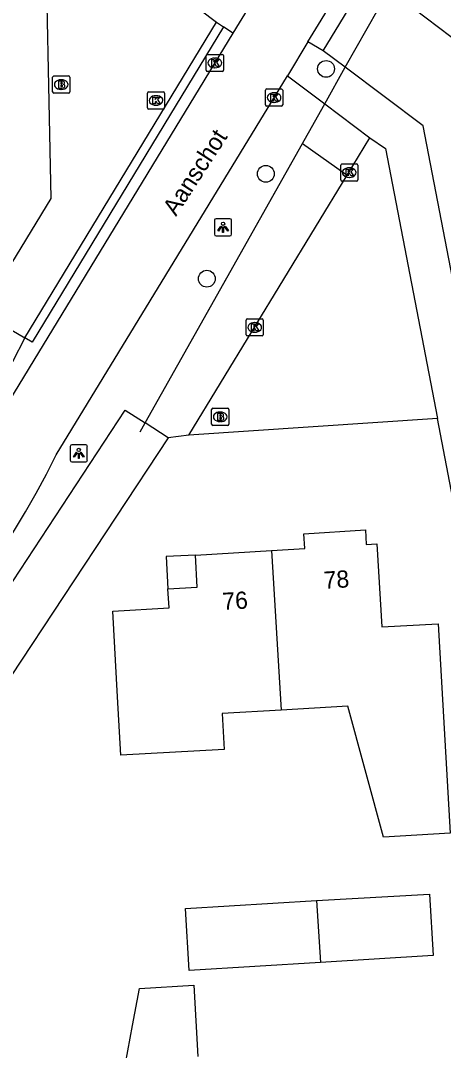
# Model space of a CAD drawing. Extents: x 159628 to 160723, y 388176 to 389416.
# Drawn here: x 160393.4 to 160418, y 388521 to 388580.9 of the extents above; entities that cross this region are included whole.
import ezdxf

# ---------------------------------------------------------------- set-up
doc = ezdxf.new("R2010")
doc.units = 0
for name, color, linetype in [('IMGEO_Berm_groen', 7, 'Continuous'), ('IMGEO_Boom', 7, 'Continuous'), ('IMGEO_Brandkraan', 7, 'Continuous'), ('IMGEO_Duiker', 7, 'Continuous'), ('IMGEO_Fietspad_gesloten', 7, 'Continuous'), ('IMGEO_Groenvoorziening', 7, 'Continuous'), ('IMGEO_Haag', 7, 'Continuous'), ('IMGEO_Kolk', 7, 'Continuous'), ('IMGEO_Lichtpunt', 7, 'Continuous'), ('IMGEO_Openbare_ruimte_label', 7, 'Continuous'), ('IMGEO_Pand', 7, 'Continuous'), ('IMGEO_Pand_nummerreeks', 7, 'Continuous'), ('IMGEO_Pand_overbouw', 7, 'Continuous'), ('IMGEO_Rijbaan_lokaal_open', 7, 'Continuous'), ('IMGEO_Voetpad_open', 7, 'Continuous'), ('IMGEO_Waterloop', 7, 'Continuous')]:
    doc.layers.add(name, color=color, linetype=linetype)

msp = doc.modelspace()

# ---------------------------------------------------------------- linework, layer by layer
at = {"layer": 'IMGEO_Berm_groen'}
for points in [[(160400.605, 388557.491), (160409.76, 388573.745), (160412.374, 388571.905)], [(160393.603, 388562.441), (160392.884, 388561.036)]]:
    msp.add_lwpolyline(points, dxfattribs=at)
at = {"layer": 'IMGEO_Boom'}
for centre in [(160411.138, 388578.087), (160407.635, 388571.983), (160404.196, 388565.881)]:
    msp.add_circle(centre, 0.489, dxfattribs=at)
at = {"layer": 'IMGEO_Brandkraan'}
for p, q in [((160395.223, 388576.751), (160395.223, 388577.603)), ((160395.298, 388577.677), (160396.15, 388577.677)), ((160395.711, 388577.457), (160395.736, 388577.457)), ((160396.224, 388577.603), (160396.224, 388576.751)), ((160395.734, 388576.897), (160395.709, 388576.897)), ((160396.15, 388576.677), (160395.298, 388576.677)), ((160404.479, 388557.418), (160404.479, 388558.27)), ((160404.554, 388558.344), (160405.406, 388558.344)), ((160405.48, 388558.27), (160405.48, 388557.418)), ((160404.99, 388557.564), (160404.965, 388557.564)), ((160404.967, 388558.124), (160404.992, 388558.124)), ((160405.406, 388557.344), (160404.554, 388557.344))]:
    msp.add_line(p, q, dxfattribs=at)
for points in [[(160395.223, 388576.751), (160395.223, 388577.603)], [(160395.298, 388577.677), (160396.15, 388577.677)], [(160395.571, 388577.377), (160395.571, 388576.977), (160395.784, 388576.977)], [(160395.802, 388577.377), (160395.571, 388577.377)], [(160396.224, 388577.603), (160396.224, 388576.751)], [(160395.75, 388577.296), (160395.696, 388577.296), (160395.696, 388577.22)], [(160395.696, 388577.22), (160395.749, 388577.22)], [(160395.758, 388577.144), (160395.696, 388577.144), (160395.696, 388577.063)], [(160395.696, 388577.063), (160395.758, 388577.063)], [(160396.15, 388576.677), (160395.298, 388576.677)], [(160404.479, 388557.418), (160404.479, 388558.27)], [(160404.554, 388558.344), (160405.406, 388558.344)], [(160405.48, 388558.27), (160405.48, 388557.418)], [(160404.827, 388558.044), (160404.827, 388557.644), (160405.04, 388557.644)], [(160405.058, 388558.044), (160404.827, 388558.044)], [(160405.006, 388557.963), (160404.952, 388557.963), (160404.952, 388557.887)], [(160404.952, 388557.887), (160405.005, 388557.887)], [(160405.014, 388557.811), (160404.952, 388557.811), (160404.952, 388557.73)], [(160404.952, 388557.73), (160405.014, 388557.73)], [(160405.406, 388557.344), (160404.554, 388557.344)]]:
    msp.add_lwpolyline(points, dxfattribs=at)
for centre, radius, start, end in [((160395.3, 388577.601), 0.0765, 91.55205, 178.44795), ((160395.3, 388577.601), 0.0765, 91.55205, 178.44795), ((160395.806, 388577.232), 0.145, 59.4692, 91.53667), ((160395.831, 388577.279), 0.0922, 285.51372, 58.15012), ((160396.148, 388577.601), 0.0765, 1.55205, 88.44795), ((160396.148, 388577.601), 0.0765, 1.55205, 88.44795), ((160395.3, 388576.753), 0.0765, 181.55205, 268.44795), ((160395.3, 388576.753), 0.0765, 181.55205, 268.44795), ((160395.751, 388577.258), 0.0379, 267.82845, 90.93552), ((160395.759, 388577.103), 0.0404, 269.87594, 90.50774), ((160395.79, 388577.228), 0.251, 268.66757, 293.53466), ((160395.836, 388577.087), 0.105, 301.31148, 78.98903), ((160396.148, 388576.753), 0.0765, 271.55205, 358.44795), ((160396.148, 388576.753), 0.0765, 271.55205, 358.44795), ((160404.556, 388558.268), 0.0765, 91.55205, 178.44795), ((160404.556, 388558.268), 0.0765, 91.55205, 178.44795), ((160405.404, 388558.268), 0.0765, 1.55205, 88.44795), ((160405.404, 388558.268), 0.0765, 1.55205, 88.44795), ((160405.007, 388557.925), 0.0379, 267.82845, 90.93552), ((160405.015, 388557.77), 0.0404, 269.87594, 90.50774), ((160405.046, 388557.895), 0.251, 268.66757, 293.53466), ((160405.062, 388557.899), 0.145, 59.4692, 91.53667), ((160405.087, 388557.946), 0.0922, 285.51372, 58.15012), ((160405.092, 388557.754), 0.105, 301.31148, 78.98903), ((160404.556, 388557.42), 0.0765, 181.55205, 268.44795), ((160404.556, 388557.42), 0.0765, 181.55205, 268.44795), ((160405.404, 388557.42), 0.0765, 271.55205, 358.44795), ((160405.404, 388557.42), 0.0765, 271.55205, 358.44795)]:
    msp.add_arc(centre, radius, start, end, dxfattribs=at)
for centre, major_axis, ratio, start_param, end_param in [((160395.71, 388577.177), (-0.387, 0.002), 0.722429, 4.712389, 7.853982), ((160395.735, 388577.177), (-0.39, 0.002), 0.717154, 1.570796, 4.712389), ((160404.966, 388557.844), (-0.387, 0.002), 0.722429, 4.712389, 7.853982), ((160404.991, 388557.844), (-0.39, 0.002), 0.717154, 1.570796, 4.712389)]:
    msp.add_ellipse(centre, major_axis=major_axis, ratio=ratio, start_param=start_param, end_param=end_param, dxfattribs=at)
at = {"layer": 'IMGEO_Duiker'}
msp.add_lwpolyline([(160400.316, 388556.978), (160400.605, 388557.491), (160411.06, 388576.054), (160412.259, 388578.184), (160414.806, 388582.706), (160416.017, 388584.856), (160416.544, 388585.792), (160416.623, 388585.932)], dxfattribs=at)
at = {"layer": 'IMGEO_Fietspad_gesloten'}
for points in [[(160406.613, 388581.63), (160405.715, 388580.159)], [(160405.715, 388580.159), (160392.155, 388557.919)], [(160410.081, 388579.662), (160408.889, 388577.691)], [(160395.428, 388555.636), (160408.889, 388577.691)]]:
    msp.add_lwpolyline(points, dxfattribs=at)
msp.add_arc((160346.289, 388579.991), 54.844, 291.95332, 333.63542, dxfattribs=at)
at = {"layer": 'IMGEO_Groenvoorziening'}
msp.add_lwpolyline([(160403.151, 388556.78), (160401.953, 388556.623)], dxfattribs=at)
at = {"layer": 'IMGEO_Haag'}
msp.add_lwpolyline([(160405.169, 388580.532), (160394.03, 388562.182), (160393.603, 388562.441)], dxfattribs=at)
at = {"layer": 'IMGEO_Kolk'}
for p, q in [((160404.163, 388578.009), (160404.163, 388578.861)), ((160404.238, 388578.935), (160405.09, 388578.935)), ((160404.651, 388578.715), (160404.676, 388578.715)), ((160405.164, 388578.861), (160405.164, 388578.009)), ((160405.09, 388577.935), (160404.238, 388577.935)), ((160404.674, 388578.155), (160404.649, 388578.155)), ((160400.814, 388576.751), (160401.666, 388576.751)), ((160407.612, 388575.994), (160407.612, 388576.846)), ((160407.687, 388576.92), (160408.539, 388576.92)), ((160408.613, 388576.846), (160408.613, 388575.994)), ((160400.739, 388575.825), (160400.739, 388576.677)), ((160401.227, 388576.531), (160401.252, 388576.531)), ((160401.74, 388576.677), (160401.74, 388575.825)), ((160408.123, 388576.14), (160408.098, 388576.14)), ((160408.1, 388576.7), (160408.125, 388576.7)), ((160401.666, 388575.751), (160400.814, 388575.751)), ((160401.25, 388575.971), (160401.225, 388575.971)), ((160408.539, 388575.92), (160407.687, 388575.92)), ((160412.066, 388572.557), (160412.918, 388572.557)), ((160411.991, 388571.631), (160411.991, 388572.483)), ((160412.479, 388572.337), (160412.504, 388572.337)), ((160412.992, 388572.483), (160412.992, 388571.631)), ((160412.918, 388571.557), (160412.066, 388571.557)), ((160412.502, 388571.777), (160412.477, 388571.777)), ((160406.559, 388563.548), (160407.411, 388563.548)), ((160406.484, 388562.622), (160406.484, 388563.474)), ((160406.972, 388563.328), (160406.997, 388563.328)), ((160407.485, 388563.474), (160407.485, 388562.622)), ((160407.411, 388562.548), (160406.559, 388562.548)), ((160406.995, 388562.768), (160406.97, 388562.768))]:
    msp.add_line(p, q, dxfattribs=at)
for points in [[(160404.163, 388578.009), (160404.163, 388578.861)], [(160404.238, 388578.935), (160405.09, 388578.935)], [(160404.484, 388578.635), (160404.607, 388578.635), (160404.607, 388578.484), (160404.737, 388578.635), (160404.901, 388578.635), (160404.755, 388578.484), (160404.908, 388578.235), (160404.756, 388578.235), (160404.671, 388578.399), (160404.607, 388578.332), (160404.607, 388578.235), (160404.484, 388578.235), (160404.484, 388578.635)], [(160405.164, 388578.861), (160405.164, 388578.009)], [(160405.09, 388577.935), (160404.238, 388577.935)], [(160400.814, 388576.751), (160401.666, 388576.751)], [(160407.612, 388575.994), (160407.612, 388576.846)], [(160407.687, 388576.92), (160408.539, 388576.92)], [(160408.613, 388576.846), (160408.613, 388575.994)], [(160400.739, 388575.825), (160400.739, 388576.677)], [(160401.06, 388576.451), (160401.183, 388576.451), (160401.183, 388576.3), (160401.313, 388576.451), (160401.477, 388576.451), (160401.331, 388576.3), (160401.484, 388576.051), (160401.332, 388576.051), (160401.247, 388576.215), (160401.183, 388576.148), (160401.183, 388576.051), (160401.06, 388576.051), (160401.06, 388576.451)], [(160401.74, 388576.677), (160401.74, 388575.825)], [(160407.933, 388576.62), (160408.056, 388576.62), (160408.056, 388576.469), (160408.186, 388576.62), (160408.35, 388576.62), (160408.204, 388576.469), (160408.357, 388576.22), (160408.205, 388576.22), (160408.12, 388576.384), (160408.056, 388576.317), (160408.056, 388576.22), (160407.933, 388576.22), (160407.933, 388576.62)], [(160401.666, 388575.751), (160400.814, 388575.751)], [(160408.539, 388575.92), (160407.687, 388575.92)], [(160412.066, 388572.557), (160412.918, 388572.557)], [(160411.991, 388571.631), (160411.991, 388572.483)], [(160412.312, 388572.257), (160412.435, 388572.257), (160412.435, 388572.106), (160412.565, 388572.257), (160412.729, 388572.257), (160412.583, 388572.106), (160412.736, 388571.857), (160412.584, 388571.857), (160412.499, 388572.021), (160412.435, 388571.954), (160412.435, 388571.857), (160412.312, 388571.857), (160412.312, 388572.257)], [(160412.992, 388572.483), (160412.992, 388571.631)], [(160412.918, 388571.557), (160412.066, 388571.557)], [(160406.559, 388563.548), (160407.411, 388563.548)], [(160406.484, 388562.622), (160406.484, 388563.474)], [(160406.805, 388563.248), (160406.928, 388563.248), (160406.928, 388563.097), (160407.058, 388563.248), (160407.222, 388563.248), (160407.076, 388563.097), (160407.229, 388562.848), (160407.077, 388562.848), (160406.992, 388563.012), (160406.928, 388562.945), (160406.928, 388562.848), (160406.805, 388562.848), (160406.805, 388563.248)], [(160407.485, 388563.474), (160407.485, 388562.622)], [(160407.411, 388562.548), (160406.559, 388562.548)]]:
    msp.add_lwpolyline(points, dxfattribs=at)
for centre, start, end in [((160404.24, 388578.859), 91.55205, 178.44795), ((160404.24, 388578.859), 91.55205, 178.44795), ((160405.088, 388578.859), 1.55205, 88.44795), ((160405.088, 388578.859), 1.55205, 88.44795), ((160404.24, 388578.011), 181.55205, 268.44795), ((160404.24, 388578.011), 181.55205, 268.44795), ((160405.088, 388578.011), 271.55205, 358.44795), ((160405.088, 388578.011), 271.55205, 358.44795), ((160400.816, 388576.675), 91.55205, 178.44795), ((160400.816, 388576.675), 91.55205, 178.44795), ((160401.664, 388576.675), 1.55205, 88.44795), ((160401.664, 388576.675), 1.55205, 88.44795), ((160407.689, 388576.844), 91.55205, 178.44795), ((160407.689, 388576.844), 91.55205, 178.44795), ((160408.537, 388576.844), 1.55205, 88.44795), ((160408.537, 388576.844), 1.55205, 88.44795), ((160400.816, 388575.827), 181.55205, 268.44795), ((160400.816, 388575.827), 181.55205, 268.44795), ((160401.664, 388575.827), 271.55205, 358.44795), ((160401.664, 388575.827), 271.55205, 358.44795), ((160407.689, 388575.996), 181.55205, 268.44795), ((160407.689, 388575.996), 181.55205, 268.44795), ((160408.537, 388575.996), 271.55205, 358.44795), ((160408.537, 388575.996), 271.55205, 358.44795), ((160412.068, 388572.481), 91.55205, 178.44795), ((160412.068, 388572.481), 91.55205, 178.44795), ((160412.916, 388572.481), 1.55205, 88.44795), ((160412.916, 388572.481), 1.55205, 88.44795), ((160412.068, 388571.633), 181.55205, 268.44795), ((160412.068, 388571.633), 181.55205, 268.44795), ((160412.916, 388571.633), 271.55205, 358.44795), ((160412.916, 388571.633), 271.55205, 358.44795), ((160406.561, 388563.472), 91.55205, 178.44795), ((160406.561, 388563.472), 91.55205, 178.44795), ((160407.409, 388563.472), 1.55205, 88.44795), ((160407.409, 388563.472), 1.55205, 88.44795), ((160406.561, 388562.624), 181.55205, 268.44795), ((160406.561, 388562.624), 181.55205, 268.44795), ((160407.409, 388562.624), 271.55205, 358.44795), ((160407.409, 388562.624), 271.55205, 358.44795)]:
    msp.add_arc(centre, 0.0765, start, end, dxfattribs=at)
for centre, major_axis, ratio, start_param, end_param in [((160404.65, 388578.435), (-0.387, 0.002), 0.722429, 4.712389, 7.853982), ((160404.675, 388578.435), (-0.39, 0.002), 0.717154, 1.570796, 4.712389), ((160401.226, 388576.251), (-0.387, 0.002), 0.722429, 4.712389, 7.853982), ((160401.251, 388576.251), (-0.39, 0.002), 0.717154, 1.570796, 4.712389), ((160408.099, 388576.42), (-0.387, 0.002), 0.722429, 4.712389, 7.853982), ((160408.124, 388576.42), (-0.39, 0.002), 0.717154, 1.570796, 4.712389), ((160412.478, 388572.057), (-0.387, 0.002), 0.722429, 4.712389, 7.853982), ((160412.503, 388572.057), (-0.39, 0.002), 0.717154, 1.570796, 4.712389), ((160406.971, 388563.048), (-0.387, 0.002), 0.722429, 4.712389, 7.853982), ((160406.996, 388563.048), (-0.39, 0.002), 0.717154, 1.570796, 4.712389)]:
    msp.add_ellipse(centre, major_axis=major_axis, ratio=ratio, start_param=start_param, end_param=end_param, dxfattribs=at)
at = {"layer": 'IMGEO_Lichtpunt'}
for p, q in [((160404.644, 388569.278), (160404.644, 388568.471)), ((160404.644, 388569.278), (160404.644, 388568.471)), ((160405.546, 388569.373), (160404.738, 388569.373)), ((160405.546, 388569.373), (160404.738, 388569.373)), ((160405.64, 388568.471), (160405.64, 388569.278)), ((160405.64, 388568.471), (160405.64, 388569.278)), ((160404.738, 388568.377), (160405.546, 388568.377)), ((160404.738, 388568.377), (160405.546, 388568.377)), ((160396.246, 388556.121), (160396.246, 388555.314)), ((160396.246, 388556.121), (160396.246, 388555.314)), ((160397.148, 388556.216), (160396.34, 388556.216)), ((160397.148, 388556.216), (160396.34, 388556.216)), ((160397.242, 388555.314), (160397.242, 388556.121)), ((160397.242, 388555.314), (160397.242, 388556.121)), ((160396.34, 388555.22), (160397.148, 388555.22)), ((160396.34, 388555.22), (160397.148, 388555.22))]:
    msp.add_line(p, q, dxfattribs=at)
for points in [[(160405.018, 388568.942), (160405.057, 388568.914), (160404.869, 388568.652), (160404.831, 388568.679), (160405.018, 388568.942)], [(160405.23, 388568.914), (160405.268, 388568.941), (160405.455, 388568.679), (160405.416, 388568.651), (160405.23, 388568.914)], [(160405.12, 388568.894), (160405.167, 388568.894), (160405.167, 388568.572), (160405.12, 388568.572), (160405.12, 388568.894)], [(160396.62, 388555.785), (160396.659, 388555.757), (160396.471, 388555.495), (160396.433, 388555.522), (160396.62, 388555.785)], [(160396.832, 388555.757), (160396.87, 388555.784), (160397.057, 388555.522), (160397.018, 388555.494), (160396.832, 388555.757)], [(160396.722, 388555.737), (160396.769, 388555.737), (160396.769, 388555.415), (160396.722, 388555.415), (160396.722, 388555.737)]]:
    msp.add_lwpolyline(points, dxfattribs=at)
for centre in [(160405.143, 388569.076), (160396.745, 388555.919)]:
    msp.add_circle(centre, 0.0994, dxfattribs=at)
for centre, start, end in [((160404.738, 388569.278), 90, 180), ((160404.738, 388569.278), 90, 180), ((160405.546, 388569.278), 0, 90), ((160405.546, 388569.278), 0, 90), ((160404.738, 388568.471), 180, 270), ((160404.738, 388568.471), 180, 270), ((160405.546, 388568.471), 270, 0), ((160405.546, 388568.471), 270, 360), ((160396.34, 388556.121), 90, 180), ((160396.34, 388556.121), 90, 180), ((160397.148, 388556.121), 0, 90), ((160397.148, 388556.121), 0, 90), ((160396.34, 388555.314), 180, 270), ((160396.34, 388555.314), 180, 270), ((160397.148, 388555.314), 270, 0), ((160397.148, 388555.314), 270, 360)]:
    msp.add_arc(centre, 0.0946, start, end, dxfattribs=at)
at = {"layer": 'IMGEO_Pand'}
for points in [[(160407.967, 388550.067), (160409.903, 388550.188), (160409.849, 388551.044), (160413.432, 388551.275), (160413.481, 388550.416), (160414.101, 388550.451), (160414.377, 388545.617), (160417.674, 388545.804), (160418.366, 388533.614), (160414.483, 388533.394), (160412.414, 388541.006), (160408.516, 388540.785)], [(160408.516, 388540.785), (160405.082, 388540.59), (160405.201, 388538.492), (160399.197, 388538.152), (160399.004, 388541.554), (160398.721, 388546.545), (160401.999, 388546.733), (160401.937, 388547.831), (160403.637, 388547.929), (160403.533, 388549.79), (160407.967, 388550.067)], [(160407.967, 388550.067), (160408.516, 388540.785)], [(160410.588, 388529.703), (160417.16, 388530.067), (160417.379, 388526.493), (160410.811, 388526.089)], [(160410.811, 388526.089), (160403.178, 388525.62), (160402.957, 388529.235), (160410.588, 388529.703)], [(160410.588, 388529.703), (160410.811, 388526.089)], [(160404.559, 388505.251), (160401.403, 388505.039), (160401.478, 388503.932), (160399.726, 388503.815), (160399.851, 388501.965), (160395.266, 388501.702), (160394.889, 388507.998), (160394.62, 388507.983), (160394.482, 388510.278), (160394.752, 388510.295), (160394.711, 388510.994), (160398.304, 388511.209), (160398.178, 388513.305), (160398.368, 388514.324), (160399.879, 388522.423), (160400.282, 388524.588), (160403.45, 388524.773), (160403.682, 388520.619)]]:
    msp.add_lwpolyline(points, dxfattribs=at)
at = {"layer": 'IMGEO_Pand_overbouw'}
msp.add_lwpolyline([(160401.937, 388547.831), (160403.637, 388547.929), (160403.533, 388549.79), (160401.833, 388549.712)], close=True, dxfattribs=at)
at = {"layer": 'IMGEO_Rijbaan_lokaal_open'}
for points in [[(160410.081, 388579.662), (160413.303, 388584.911)], [(160410.98, 388579.143), (160413.658, 388583.58)], [(160413.658, 388583.58), (160414.806, 388582.706), (160419.837, 388578.879), (160420.072, 388578.69)], [(160410.98, 388579.143), (160410.081, 388579.662)], [(160421.804, 388548.844), (160416.794, 388574.782), (160412.259, 388578.184), (160410.98, 388579.143)]]:
    msp.add_lwpolyline(points, dxfattribs=at)
at = {"layer": 'IMGEO_Voetpad_open'}
for points in [[(160391.082, 388563.91), (160395.137, 388570.551), (160394.778, 388588.369)], [(160394.778, 388588.369), (160404.756, 388580.814)], [(160393.603, 388562.441), (160404.756, 388580.814)], [(160404.756, 388580.814), (160405.169, 388580.532)], [(160405.715, 388580.159), (160405.169, 388580.532)], [(160408.889, 388577.691), (160411.06, 388576.054), (160413.693, 388574.069)], [(160412.374, 388571.905), (160413.693, 388574.069)], [(160413.693, 388574.069), (160414.591, 388573.459), (160417.623, 388557.739)], [(160403.151, 388556.78), (160412.374, 388571.905)], [(160391.082, 388563.91), (160393.603, 388562.441)], [(160417.623, 388557.739), (160403.151, 388556.78)], [(160428.536, 388500), (160428.603, 388500.275), (160428.603, 388500.573), (160427.081, 388508.495), (160423.552, 388526.872), (160417.623, 388557.739)]]:
    msp.add_lwpolyline(points, dxfattribs=at)
at = {"layer": 'IMGEO_Waterloop'}
for points in [[(160390.866, 388545.19), (160399.448, 388558.235), (160400.605, 388557.491)], [(160401.953, 388556.623), (160400.605, 388557.491)], [(160401.953, 388556.623), (160392.807, 388542.778)]]:
    msp.add_lwpolyline(points, dxfattribs=at)

# ---------------------------------------------------------------- texts
at = {"layer": 'IMGEO_Openbare_ruimte_label'}
msp.add_text('Aanschot', height=1, rotation=57.04099, dxfattribs=at).set_placement((160402.404, 388569.47))
at = {"layer": 'IMGEO_Pand_nummerreeks'}
for s, rotation, p in [('78', 3.68882, (160411.03, 388547.834)), ('76', 3.57521, (160405.13, 388546.603))]:
    msp.add_text(s, height=1, rotation=rotation, dxfattribs=at).set_placement(p)

doc.saveas('drawing.dxf')
